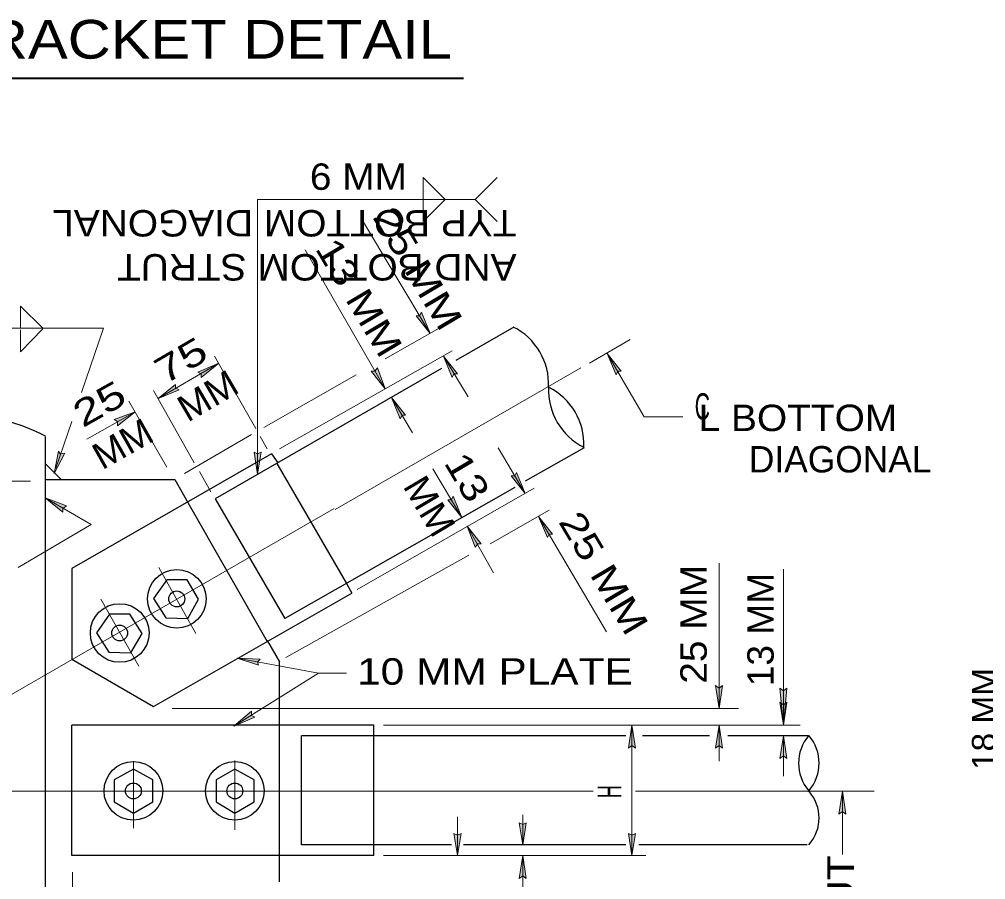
# Model space of a CAD drawing. Extents: x 312601.858 to 312602.699, y 144420.109 to 144420.704.
# Drawn here: x 312602.1684 to 312602.2782, y 144420.4155 to 144420.5132 of the extents above; entities that cross this region are included whole.
import ezdxf
from ezdxf.enums import TextEntityAlignment as Align

# ---------------------------------------------------------------- set-up
doc = ezdxf.new("R2010")
doc.units = 0
doc.header["$LTSCALE"] = 0.0012
doc.linetypes.add('DOT_DASHED', pattern=[7.7, 5, -1.2, 0.3, -1.2])
doc.linetypes.add('MEDIUM_DASHED', pattern=[4.5, 3, -1.5])
for name, color, linetype, lineweight in [('1', 7, 'Continuous', 25), ('2', 7, 'Continuous', 13), ('39', 7, 'Continuous', 13), ('9', 7, 'Continuous', 13)]:
    doc.layers.add(name, color=color, linetype=linetype, lineweight=lineweight)

msp = doc.modelspace()

# ---------------------------------------------------------------- hatches: boundary and pattern name
at = {"layer": '39'}
for points in [[(312602.2139, 144420.4795), (312602.2135, 144420.4795), (312602.2151, 144420.4775), (312602.2141, 144420.4799)], [(312602.2178, 144420.4729), (312602.2182, 144420.4729), (312602.2166, 144420.4749), (312602.2176, 144420.4725)], [(312602.2364, 144420.4732), (312602.2368, 144420.4732), (312602.2352, 144420.4752), (312602.2362, 144420.4728)], [(312602.1891, 144420.4729), (312602.1891, 144420.4725), (312602.1911, 144420.4741), (312602.1887, 144420.4731)], [(312602.1891, 144420.4729), (312602.1891, 144420.4725), (312602.1911, 144420.4741), (312602.1887, 144420.4731)], [(312602.2088, 144420.4732), (312602.2084, 144420.4732), (312602.21, 144420.4712), (312602.2091, 144420.4736)], [(312602.2088, 144420.4732), (312602.2084, 144420.4732), (312602.21, 144420.4712), (312602.2091, 144420.4736)], [(312602.1862, 144420.4713), (312602.1862, 144420.4717), (312602.1842, 144420.4701), (312602.1866, 144420.4711)], [(312602.1862, 144420.4713), (312602.1862, 144420.4717), (312602.1842, 144420.4701), (312602.1866, 144420.4711)], [(312602.2119, 144420.4682), (312602.2123, 144420.4682), (312602.2107, 144420.4702), (312602.2117, 144420.4678)], [(312602.2119, 144420.4682), (312602.2123, 144420.4682), (312602.2107, 144420.4702), (312602.2117, 144420.4678)], [(312602.1796, 144420.4675), (312602.1796, 144420.467), (312602.1816, 144420.4686), (312602.1792, 144420.4677)], [(312602.1731, 144420.4638), (312602.1729, 144420.4641), (312602.1724, 144420.4616), (312602.1736, 144420.4639)], [(312602.1955, 144420.4638), (312602.1951, 144420.464), (312602.1955, 144420.4615), (312602.1959, 144420.464)], [(312602.2247, 144420.4613), (312602.2243, 144420.4613), (312602.2259, 144420.4593), (312602.2249, 144420.4617)], [(312602.2247, 144420.4613), (312602.2243, 144420.4613), (312602.2259, 144420.4593), (312602.2249, 144420.4617)], [(312602.1734, 144420.4576), (312602.1738, 144420.4579), (312602.1714, 144420.4588), (312602.1734, 144420.4572)], [(312602.2175, 144420.4586), (312602.2171, 144420.4586), (312602.2187, 144420.4566), (312602.2177, 144420.459)], [(312602.2175, 144420.4586), (312602.2171, 144420.4586), (312602.2187, 144420.4566), (312602.2177, 144420.459)], [(312602.2286, 144420.4547), (312602.229, 144420.4547), (312602.2274, 144420.4567), (312602.2284, 144420.4543)], [(312602.2286, 144420.4547), (312602.229, 144420.4547), (312602.2274, 144420.4567), (312602.2284, 144420.4543)], [(312602.2205, 144420.4536), (312602.2209, 144420.4536), (312602.2193, 144420.4556), (312602.2202, 144420.4532)], [(312602.2205, 144420.4536), (312602.2209, 144420.4536), (312602.2193, 144420.4556), (312602.2202, 144420.4532)], [(312602.1955, 144420.4402), (312602.1956, 144420.4398), (312602.1932, 144420.4406), (312602.1958, 144420.4405)], [(312602.2479, 144420.4372), (312602.2483, 144420.4375), (312602.2479, 144420.4349), (312602.2475, 144420.4375)], [(312602.2552, 144420.4369), (312602.2548, 144420.4372), (312602.2552, 144420.433), (312602.2556, 144420.4372)], [(312602.2552, 144420.4353), (312602.2556, 144420.4356), (312602.2552, 144420.433), (312602.2548, 144420.4356)], [(312602.1948, 144420.4341), (312602.1952, 144420.4339), (312602.1928, 144420.4329), (312602.1948, 144420.4346)], [(312602.238, 144420.4307), (312602.2384, 144420.4304), (312602.238, 144420.433), (312602.2376, 144420.4304)], [(312602.2479, 144420.4307), (312602.2483, 144420.4304), (312602.2479, 144420.433), (312602.2475, 144420.4304)], [(312602.2552, 144420.4295), (312602.2556, 144420.4292), (312602.2552, 144420.4318), (312602.2548, 144420.4292)], [(312602.2552, 144420.4295), (312602.2556, 144420.4292), (312602.2552, 144420.4318), (312602.2548, 144420.4292)], [(312602.2619, 144420.4232), (312602.2623, 144420.4229), (312602.2619, 144420.4255), (312602.2615, 144420.4229)], [(312602.2256, 144420.4217), (312602.2252, 144420.4219), (312602.2256, 144420.4194), (312602.226, 144420.4219)], [(312602.2182, 144420.4205), (312602.2178, 144420.4207), (312602.2182, 144420.4182), (312602.2186, 144420.4207)], [(312602.238, 144420.4205), (312602.2376, 144420.4207), (312602.238, 144420.4182), (312602.2384, 144420.4207)], [(312602.2256, 144420.4159), (312602.226, 144420.4156), (312602.2256, 144420.4182), (312602.2252, 144420.4156)], [(312602.2256, 144420.4159), (312602.226, 144420.4156), (312602.2256, 144420.4182), (312602.2252, 144420.4156)]]:
    msp.add_hatch(color=256, dxfattribs=at).paths.add_polyline_path(points)

# ---------------------------------------------------------------- linework, layer by layer
at = {"layer": '1', "lineweight": 13}
for p, q in [((312602.2073, 144420.4905), (312602.2151, 144420.4775)), ((312602.2009, 144420.487), (312602.21, 144420.4712)), ((312602.2161, 144420.4781), (312602.21, 144420.4746)), ((312602.2332, 144420.4741), (312602.2378, 144420.4768)), ((312602.1906, 144420.4749), (312602.1953, 144420.4667)), ((312602.2176, 144420.4755), (312602.198, 144420.4644)), ((312602.2166, 144420.4749), (312602.2194, 144420.4703)), ((312602.1911, 144420.4741), (312602.1842, 144420.4701)), ((312602.2067, 144420.4728), (312602.1962, 144420.4668)), ((312602.1837, 144420.471), (312602.1883, 144420.4628)), ((312602.1809, 144420.4698), (312602.1852, 144420.4623)), ((312602.2107, 144420.4702), (312602.2131, 144420.4662)), ((312602.1816, 144420.4686), (312602.1761, 144420.4655)), ((312602.1948, 144420.466), (312602.1872, 144420.4616)), ((312602.1958, 144420.4658), (312602.1966, 144420.4644)), ((312602.2228, 144420.4645), (312602.2259, 144420.4593)), ((312602.1889, 144420.4618), (312602.1902, 144420.4595)), ((312602.2154, 144420.4621), (312602.2187, 144420.4566)), ((312602.1384, 144420.4607), (312602.1697, 144420.4607)), ((312602.2269, 144420.4599), (312602.2068, 144420.4484)), ((312602.2286, 144420.4574), (312602.2219, 144420.4536)), ((312602.2274, 144420.4567), (312602.2351, 144420.4436)), ((312602.2193, 144420.4556), (312602.2223, 144420.4503)), ((312602.2195, 144420.4523), (312602.1987, 144420.4407)), ((312602.2479, 144420.4349), (312602.2479, 144420.4514)), ((312602.2552, 144420.433), (312602.2552, 144420.4507)), ((312602.2024, 144420.4389), (312602.2056, 144420.4389)), ((312602.2501, 144420.4349), (312602.1858, 144420.4349)), ((312602.2571, 144420.433), (312602.2098, 144420.433)), ((312602.238, 144420.4182), (312602.238, 144420.433)), ((312602.2479, 144420.4289), (312602.2479, 144420.433)), ((312602.2552, 144420.4272), (312602.2552, 144420.4318)), ((312602.2507, 144420.4255), (312602.2655, 144420.4255)), ((312602.2619, 144420.4183), (312602.2619, 144420.4255)), ((312602.2182, 144420.4182), (312602.2182, 144420.4226)), ((312602.2256, 144420.4194), (312602.2256, 144420.4228)), ((312602.2396, 144420.4182), (312602.2098, 144420.4182)), ((312602.2256, 144420.4001), (312602.2256, 144420.4182)), ((312602.1745, 144420.3905), (312602.1745, 144420.4163))]:
    msp.add_line(p, q, dxfattribs=at)
at = {"layer": '1'}
for p, q in [((312602.2246, 144420.4782), (312602.218, 144420.4744)), ((312602.2164, 144420.4735), (312602.1907, 144420.4587)), ((312602.1714, 144420.4658), (312602.1714, 144420.3874)), ((312602.1971, 144420.4638), (312602.1978, 144420.4628)), ((312602.2326, 144420.4645), (312602.2259, 144420.4607)), ((312602.1714, 144420.4609), (312602.1861, 144420.4609)), ((312602.1861, 144420.4609), (312602.1876, 144420.4583)), ((312602.2247, 144420.46), (312602.1986, 144420.4451)), ((312602.1907, 144420.4587), (312602.1986, 144420.4451)), ((312602.2056, 144420.4491), (312602.2062, 144420.448)), ((312602.1966, 144420.4426), (312602.198, 144420.4402)), ((312602.198, 144420.433), (312602.198, 144420.4402)), ((312602.1744, 144420.4182), (312602.1744, 144420.433)), ((312602.2087, 144420.433), (312602.1744, 144420.433)), ((312602.2087, 144420.4318), (312602.2087, 144420.433)), ((312602.2005, 144420.4194), (312602.2005, 144420.4318)), ((312602.2373, 144420.4318), (312602.2005, 144420.4318)), ((312602.2468, 144420.4318), (312602.2392, 144420.4318)), ((312602.258, 144420.4318), (312602.2489, 144420.4318)), ((312602.2175, 144420.4194), (312602.2005, 144420.4194)), ((312602.2087, 144420.4182), (312602.2087, 144420.4194)), ((312602.2373, 144420.4194), (312602.2189, 144420.4194)), ((312602.2579, 144420.4194), (312602.2388, 144420.4194)), ((312602.2087, 144420.4182), (312602.1744, 144420.4182)), ((312602.198, 144420.4152), (312602.198, 144420.4182))]:
    msp.add_line(p, q, dxfattribs=at)
at = {"layer": '1', "linetype": 'DOT_DASHED', "lineweight": 13}
for p, q in [((312602.2043, 144420.4575), (312602.2322, 144420.4736)), ((312602.1471, 144420.4247), (312602.2042, 144420.4576)), ((312602.1885, 144420.4434), (312602.1843, 144420.4509)), ((312602.182, 144420.4397), (312602.1777, 144420.4473)), ((312602.1814, 144420.4213), (312602.1814, 144420.4289)), ((312602.1929, 144420.4211), (312602.1929, 144420.429)), ((312602.1469, 144420.4255), (312602.2336, 144420.4255)), ((312602.2384, 144420.4255), (312602.258, 144420.4255))]:
    msp.add_line(p, q, dxfattribs=at)
at = {"layer": '1', "linetype": 'MEDIUM_DASHED'}
for p, q in [((312602.1977, 144420.4627), (312602.2056, 144420.4491)), ((312602.1876, 144420.4583), (312602.1966, 144420.4425)), ((312602.198, 144420.4182), (312602.198, 144420.433)), ((312602.2087, 144420.4194), (312602.2087, 144420.4318))]:
    msp.add_line(p, q, dxfattribs=at)
at = {"layer": '1', "lineweight": 13}
for points in [[(312602.2352, 144420.4752), (312602.2394, 144420.468), (312602.2438, 144420.468)], [(312602.1932, 144420.4406), (312602.2024, 144420.4389), (312602.1928, 144420.4329)]]:
    msp.add_lwpolyline(points, dxfattribs=at)
at = {"layer": '1'}
msp.add_lwpolyline([(312602.1971, 144420.4638), (312602.1744, 144420.4508), (312602.1744, 144420.4405), (312602.1837, 144420.4351), (312602.2062, 144420.448)], dxfattribs=at)
for points in [[(312602.1876, 144420.4451), (312602.1888, 144420.4473), (312602.1875, 144420.4495), (312602.1852, 144420.4495), (312602.1837, 144420.4474), (312602.1851, 144420.4452)], [(312602.1811, 144420.4412), (312602.1824, 144420.4434), (312602.181, 144420.4456), (312602.1787, 144420.4456), (312602.1772, 144420.4435), (312602.1786, 144420.4413)], [(312602.1814, 144420.428), (312602.1792, 144420.4268), (312602.1792, 144420.4243), (312602.1814, 144420.423), (312602.1836, 144420.4243), (312602.1836, 144420.4268)], [(312602.1929, 144420.428), (312602.1908, 144420.4268), (312602.1908, 144420.4243), (312602.1929, 144420.423), (312602.1951, 144420.4243), (312602.1951, 144420.4268)]]:
    msp.add_lwpolyline(points, close=True, dxfattribs=at)
for centre, radius in [((312602.186324, 144420.447337), 0.00333), ((312602.186324, 144420.447337), 0.0009), ((312602.179844, 144420.443467), 0.00333), ((312602.179844, 144420.443467), 0.0009), ((312602.1814, 144420.42553), 0.00333), ((312602.19292, 144420.42553), 0.00333), ((312602.1814, 144420.42553), 0.0009), ((312602.19292, 144420.42553), 0.0009)]:
    msp.add_circle(centre, radius, dxfattribs=at)
at = {"layer": '2', "lineweight": 40}
msp.add_line((312602.143, 144420.5065), (312602.2189, 144420.5065), dxfattribs=at)
at = {"layer": '2'}
for p, q in [((312602.178, 144420.4781), (312602.1644, 144420.4781)), ((312602.1755, 144420.4708), (312602.178, 144420.4781)), ((312602.1726, 144420.4622), (312602.1744, 144420.4675))]:
    msp.add_line(p, q, dxfattribs=at)
msp.add_lwpolyline([(312602.2143, 144420.4902), (312602.2143, 144420.4952), (312602.2168, 144420.4927)], close=True, dxfattribs=at)
for points in [[(312602.2227, 144420.4952), (312602.2202, 144420.4927), (312602.2227, 144420.4902)], [(312602.1955, 144420.4615), (312602.1955, 144420.4927), (312602.2202, 144420.4927)], [(312602.1686, 144420.4781), (312602.1686, 144420.4806), (312602.1711, 144420.4781)], [(312602.1686, 144420.4779), (312602.1686, 144420.4754), (312602.1711, 144420.478)], [(312602.1683, 144420.4509), (312602.1766, 144420.4558), (312602.1714, 144420.4588)]]:
    msp.add_lwpolyline(points, dxfattribs=at)
at = {"layer": '2', "lineweight": 25}
for centre, radius, start, end in [((312602.221272, 144420.471715), 0.007275, 357.43281, 63.3914), ((312602.235807, 144420.471064), 0.007275, 177.43281, 243.3914), ((312602.225281, 144420.464885), 0.007275, 357.43281, 63.3914), ((312602.159935, 144420.442941), 0.025613, 63.38393, 116.61607)]:
    msp.add_arc(centre, radius, start, end, dxfattribs=at)
for centre, major_axis, ratio in [((312602.264193, 144420.428684), (-0.007275, 0), 0.79798), ((312602.251987, 144420.428684), (0.007275, 0), 0.79798), ((312602.251987, 144420.422463), (0.007275, 0), 0.772727)]:
    msp.add_ellipse(centre, major_axis=major_axis, ratio=ratio, start_param=5.707588, end_param=6.8587826, dxfattribs=at)
at = {"layer": '39'}
for points in [[(312602.2139, 144420.4795), (312602.2135, 144420.4795), (312602.2151, 144420.4775), (312602.2141, 144420.4799)], [(312602.2178, 144420.4729), (312602.2182, 144420.4729), (312602.2166, 144420.4749), (312602.2176, 144420.4725)], [(312602.2364, 144420.4732), (312602.2368, 144420.4732), (312602.2352, 144420.4752), (312602.2362, 144420.4728)], [(312602.1891, 144420.4729), (312602.1891, 144420.4725), (312602.1911, 144420.4741), (312602.1887, 144420.4731)], [(312602.1891, 144420.4729), (312602.1891, 144420.4725), (312602.1911, 144420.4741), (312602.1887, 144420.4731)], [(312602.2088, 144420.4732), (312602.2084, 144420.4732), (312602.21, 144420.4712), (312602.2091, 144420.4736)], [(312602.2088, 144420.4732), (312602.2084, 144420.4732), (312602.21, 144420.4712), (312602.2091, 144420.4736)], [(312602.1862, 144420.4713), (312602.1862, 144420.4717), (312602.1842, 144420.4701), (312602.1866, 144420.4711)], [(312602.1862, 144420.4713), (312602.1862, 144420.4717), (312602.1842, 144420.4701), (312602.1866, 144420.4711)], [(312602.2119, 144420.4682), (312602.2123, 144420.4682), (312602.2107, 144420.4702), (312602.2117, 144420.4678)], [(312602.2119, 144420.4682), (312602.2123, 144420.4682), (312602.2107, 144420.4702), (312602.2117, 144420.4678)], [(312602.1796, 144420.4675), (312602.1796, 144420.467), (312602.1816, 144420.4686), (312602.1792, 144420.4677)], [(312602.1731, 144420.4638), (312602.1729, 144420.4641), (312602.1724, 144420.4616), (312602.1736, 144420.4639)], [(312602.1955, 144420.4638), (312602.1951, 144420.464), (312602.1955, 144420.4615), (312602.1959, 144420.464)], [(312602.2247, 144420.4613), (312602.2243, 144420.4613), (312602.2259, 144420.4593), (312602.2249, 144420.4617)], [(312602.2247, 144420.4613), (312602.2243, 144420.4613), (312602.2259, 144420.4593), (312602.2249, 144420.4617)], [(312602.1734, 144420.4576), (312602.1738, 144420.4579), (312602.1714, 144420.4588), (312602.1734, 144420.4572)], [(312602.2175, 144420.4586), (312602.2171, 144420.4586), (312602.2187, 144420.4566), (312602.2177, 144420.459)], [(312602.2175, 144420.4586), (312602.2171, 144420.4586), (312602.2187, 144420.4566), (312602.2177, 144420.459)], [(312602.2286, 144420.4547), (312602.229, 144420.4547), (312602.2274, 144420.4567), (312602.2284, 144420.4543)], [(312602.2286, 144420.4547), (312602.229, 144420.4547), (312602.2274, 144420.4567), (312602.2284, 144420.4543)], [(312602.2205, 144420.4536), (312602.2209, 144420.4536), (312602.2193, 144420.4556), (312602.2202, 144420.4532)], [(312602.2205, 144420.4536), (312602.2209, 144420.4536), (312602.2193, 144420.4556), (312602.2202, 144420.4532)], [(312602.1955, 144420.4402), (312602.1956, 144420.4398), (312602.1932, 144420.4406), (312602.1958, 144420.4405)], [(312602.2479, 144420.4372), (312602.2483, 144420.4375), (312602.2479, 144420.4349), (312602.2475, 144420.4375)], [(312602.2552, 144420.4369), (312602.2548, 144420.4372), (312602.2552, 144420.433), (312602.2556, 144420.4372)], [(312602.2552, 144420.4353), (312602.2556, 144420.4356), (312602.2552, 144420.433), (312602.2548, 144420.4356)], [(312602.1948, 144420.4341), (312602.1952, 144420.4339), (312602.1928, 144420.4329), (312602.1948, 144420.4346)], [(312602.238, 144420.4307), (312602.2384, 144420.4304), (312602.238, 144420.433), (312602.2376, 144420.4304)], [(312602.2479, 144420.4307), (312602.2483, 144420.4304), (312602.2479, 144420.433), (312602.2475, 144420.4304)], [(312602.2552, 144420.4295), (312602.2556, 144420.4292), (312602.2552, 144420.4318), (312602.2548, 144420.4292)], [(312602.2552, 144420.4295), (312602.2556, 144420.4292), (312602.2552, 144420.4318), (312602.2548, 144420.4292)], [(312602.2619, 144420.4232), (312602.2623, 144420.4229), (312602.2619, 144420.4255), (312602.2615, 144420.4229)], [(312602.2256, 144420.4217), (312602.2252, 144420.4219), (312602.2256, 144420.4194), (312602.226, 144420.4219)], [(312602.2182, 144420.4205), (312602.2178, 144420.4207), (312602.2182, 144420.4182), (312602.2186, 144420.4207)], [(312602.238, 144420.4205), (312602.2376, 144420.4207), (312602.238, 144420.4182), (312602.2384, 144420.4207)], [(312602.2256, 144420.4159), (312602.226, 144420.4156), (312602.2256, 144420.4182), (312602.2252, 144420.4156)], [(312602.2256, 144420.4159), (312602.226, 144420.4156), (312602.2256, 144420.4182), (312602.2252, 144420.4156)]]:
    msp.add_lwpolyline(points, close=True, dxfattribs=at)
at = {"layer": '9'}
msp.add_lwpolyline([(312602.1714, 144420.4627), (312602.1714, 144420.4609), (312602.1732, 144420.4609)], close=True, dxfattribs=at)

# ---------------------------------------------------------------- texts
at = {"layer": '1', "width": 1.2}
msp.add_text('10 MM PLATE', height=0.003, dxfattribs=at).set_placement((312602.2068, 144420.4376))
at = {"layer": '1', "width": 1.05}
msp.add_text('18 MM', height=0.0027, rotation=90, dxfattribs=at).set_placement((312602.2793, 144420.4337), align=Align.CENTER)
at = {"layer": '2'}
for s, height, width, p in [('TOP BRACKET DETAIL', 0.0044, 1.15, (312602.1809, 144420.5087)), ('6 MM', 0.003, 1.1, (312602.20695, 144420.4938)), ('C', 0.003, 0.6, (312602.246, 144420.4677)), ('L BOTTOM', 0.003, 1.1, (312602.25685, 144420.4664))]:
    msp.add_text(s, height=height, dxfattribs=dict(at, width=width)).set_placement(p, align=Align.CENTER)
at = {"layer": '2', "width": 1.1}
for s, p in [('TYP BOTTOM DIAGONAL', (312602.2249, 144420.4915)), ('AND BOTTOM STRUT', (312602.2249, 144420.4865))]:
    msp.add_text(s, height=0.003, rotation=180, dxfattribs=at).set_placement(p)
at = {"layer": '2'}
for s, height, rotation, width, p in [('25 MM', 0.003, 300.717, 1.25, (312602.212412, 144420.484116)), ('13 MM', 0.003, 300.717, 1.2, (312602.205734, 144420.480816)), ('75', 0.003, 30.364, 1.35, (312602.187542, 144420.473148)), ('MM', 0.003, 30.364, 1.05, (312602.190592, 144420.469111)), ('25', 0.003, 29.424, 1.35, (312602.178263, 144420.468202)), ('MM', 0.003, 29.424, 1.05, (312602.180913, 144420.463656)), ('13', 0.003, 300.717, 1.25, (312602.218016, 144420.460416)), ('MM', 0.003, 300.717, 1.05, (312602.213732, 144420.457116)), ('25 MM', 0.003, 300.717, 1.25, (312602.233512, 144420.449516)), ('25 MM', 0.003, 90, 1.1, (312602.2465, 144420.44445)), ('13 MM', 0.003, 90, 1.05, (312602.2541, 144420.44385)), ('H', 0.0027, 90, 0.55, (312602.2368, 144420.42545)), ('L BOTTOM STRUT', 0.003, 90, 1.15, (312602.2632, 144420.3981))]:
    msp.add_text(s, height=height, rotation=rotation, dxfattribs=dict(at, width=width)).set_placement(p, align=Align.CENTER)
msp.add_text('DIAGONAL', height=0.003, dxfattribs=at).set_placement((312602.26165, 144420.4617), align=Align.CENTER)

doc.saveas('drawing.dxf')
